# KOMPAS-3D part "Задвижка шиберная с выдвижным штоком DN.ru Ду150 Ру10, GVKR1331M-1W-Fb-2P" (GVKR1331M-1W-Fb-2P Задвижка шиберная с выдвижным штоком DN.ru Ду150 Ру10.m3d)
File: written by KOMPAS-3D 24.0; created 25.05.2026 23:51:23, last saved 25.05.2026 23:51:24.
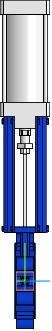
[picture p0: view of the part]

Document properties: Автор: R2D2; Полное имя файла: E:\Работа\Зайцев\GVKR1331M-1W-Fb-2P Задвижка шиберная с выдвижным штоком DN.ru Ду50-300 Ру16-10-6 с пневмоприводом\исходные материалы\DN150\DN150\GVKR1331M-1W-Fb-2P Задвижка шиберная с выдвижным штоком DN.ru Ду150 Ру10.m3d

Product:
- Part/product: Задвижка шиберная с выдвижным штоком DN.ru Ду150 Ру10  | designation GVKR1331M-1W-Fb-2P
    Масса: 23
    Раздел спецификации: Прочие изделия
    Примечание: D040-08796

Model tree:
1. Операция без истории:1

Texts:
  GVKR1331M-1W-Fb-2P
